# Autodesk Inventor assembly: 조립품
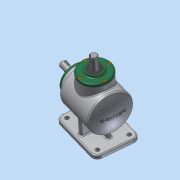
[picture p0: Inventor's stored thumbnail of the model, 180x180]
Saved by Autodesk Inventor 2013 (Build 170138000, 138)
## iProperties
Created: 2016-09
Part Number: 조립품
Document SubType Name: Assembly
Designer: dgall
Author: dgall
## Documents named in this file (14)
- C:\Users\dgall\Documents\Inventor\460907V1017\조립품.iam
- C:\Users\dgall\Documents\Inventor\460907V1017\본체.ipt
- C:\Users\dgall\Documents\Inventor\460907V1017\M4.ipt
- C:\Users\dgall\Documents\Inventor\460907V1017\메인 베벨기어.ipt
- C:\Users\dgall\Documents\Inventor\460907V1017\메인 축.ipt
- 메인 축.ipt
- C:\Users\dgall\Documents\Inventor\460907V1017\베어링 6203.ipt
- C:\Users\dgall\Documents\Inventor\460907V1017\서브 베벨기어.ipt
- C:\Users\dgall\Documents\Inventor\460907V1017\서브 축.ipt
- 서브 축.ipt
- C:\Users\dgall\Documents\Inventor\460907V1017\오일실 17 32 8.ipt
- C:\Users\dgall\Documents\Inventor\460907V1017\커버.ipt
- C:\Users\dgall\Documents\Inventor\460907V1017\키 4x4.ipt
- C:\Users\dgall\Documents\Inventor\460907V1017\키 5x5.ipt
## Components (8 placed, 1 different names)
1. M4:1
2. M4:2
3. M4:3
4. M4:4
5. M4:5
6. M4:6
7. M4:7
8. M4:8
